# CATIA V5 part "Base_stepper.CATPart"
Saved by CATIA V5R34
Part number: Part1.1
Bounding box of the stored display mesh (mm): x -123.1 to 123.1, y -33.1 to 28.1, z -50 to 0
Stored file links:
  C:\Users\Apolinar\Desktop\cnc\Base_stepper.CATPart
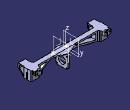
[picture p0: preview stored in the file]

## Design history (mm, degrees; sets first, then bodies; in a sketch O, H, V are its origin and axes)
AxisSystem1: origin (0, 0, 0), X (1, 0, 0), Y (0, 1, 0), Z (0, 0, 1)
Body1 (main body)
  DatumCurve1 to DatumCurve4
  Sketch1 on XY plane of AxisSystem1, origin (0, 0, 0), H (1, 0, 0), V (0, 1, 0)
    line L1 (-96.9, 10) -> (-96.9, 10.9787)
    line L2 (-99.0213, 13.1) -> (-120.9787, 13.1)
    line L3 (-123.1, 10.9787) -> (-123.1, 0)
    point P1 (-110, 0)
    arc A1 centre (-93.9, 10) radius 3 from (-93.9, 7) to (-96.9, 10) cw
    point P2 (-93.9, 7)
    point P3 (-96.9, 10)
    line L4 (-120.9787, 13.1) -> (-123.1, 10.9787)
    point P5 (-120.9787, 13.1)
    point P6 (-123.1, 10.9787)
    line L5 (-96.9, 10.9787) -> (-99.0213, 13.1)
    point P7 (-96.9, 10.9787)
    point P8 (-99.0213, 13.1)
    line L6 (-93.9, 7) -> (-93.9, 0)
    axis line L7 (-70.1752, 0) -> (-129.1057, 0)
    point P9 (-70.1752, 0)
    point P10 (-129.1057, 0)
    point P11 (-93.9, 0)
    point P12 (-123.1, 0)
    reference projected line E1 (-120, 3.75) -> (-120, 8.5) from edge of DatumCurve1
    point P13 (-93.9, -7)
    point P14 (-96.9, -10)
    point P16 (-120.9787, -13.1)
    point P17 (-123.1, -10.9787)
    point P18 (-96.9, -10.9787)
    point P19 (-99.0213, -13.1)
    line L8 (-96.9, -10) -> (-96.9, -10.9787)
    line L9 (-99.0213, -13.1) -> (-120.9787, -13.1)
    arc A2 centre (-93.9, -10) radius 3 from (-93.9, -7) to (-96.9, -10) ccw
    line L10 (-120.9787, -13.1) -> (-123.1, -10.9787)
    line L11 (-96.9, -10.9787) -> (-99.0213, -13.1)
    point P20 (-93.9, 0)
    line L12 (-93.9, -7) -> (-93.9, 0)
    point P21 (-123.1, 0)
    line L13 (-123.1, -10.9787) -> (-123.1, 0)
    point P22 (-110, 0)
    line L14 (-99.9, 10.1) -> (-99.9, -10.1)
    line L15 (-99.9, -10.1) -> (-120.1, -10.1)
    line L16 (-120.1, -10.1) -> (-120.1, 10.1)
    line L17 (-120.1, 10.1) -> (-99.9, 10.1)
    point P23 (-99.9, 10.1)
    point P24 (-99.9, -10.1)
    point P25 (-120.1, -10.1)
    point P26 (-120.1, 10.1)
    reference projected line E2 (-113.75, 10) -> (-118.5, 10) from edge of DatumCurve2
    reference projected line E3 (-100, -8.5) -> (-100, -3.75) from edge of DatumCurve3
    reference projected line E4 (-120, -8.5) -> (-120, -3.75) from edge of DatumCurve4
    point P27 (110, 0)
    point P28 (93.9, 7)
    point P29 (96.9, 10)
    point P31 (120.9787, 13.1)
    point P32 (123.1, 10.9787)
    point P33 (96.9, 10.9787)
    point P34 (99.0213, 13.1)
    point P35 (129.1057, 0)
    point P36 (93.9, 0)
    point P37 (123.1, 0)
    point P38 (93.9, -7)
    point P39 (96.9, -10)
    point P41 (120.9787, -13.1)
    point P42 (123.1, -10.9787)
    point P43 (96.9, -10.9787)
    point P44 (99.0213, -13.1)
    point P45 (93.9, 0)
    point P46 (123.1, 0)
    point P47 (110, 0)
    point P48 (99.9, 10.1)
    point P49 (99.9, -10.1)
    point P50 (120.1, -10.1)
    point P51 (120.1, 10.1)
    line L18 (96.9, 10) -> (96.9, 10.9787)
    line L19 (99.0213, 13.1) -> (120.9787, 13.1)
    line L20 (123.1, 10.9787) -> (123.1, 0)
    arc A3 centre (93.9, 10) radius 3 from (93.9, 7) to (96.9, 10) ccw
    line L21 (120.9787, 13.1) -> (123.1, 10.9787)
    line L22 (96.9, 10.9787) -> (99.0213, 13.1)
    line L23 (93.9, 7) -> (93.9, 0)
    line L24 (96.9, -10) -> (96.9, -10.9787)
    line L25 (99.0213, -13.1) -> (120.9787, -13.1)
    arc A4 centre (93.9, -10) radius 3 from (93.9, -7) to (96.9, -10) cw
    line L26 (120.9787, -13.1) -> (123.1, -10.9787)
    line L27 (96.9, -10.9787) -> (99.0213, -13.1)
    line L28 (93.9, -7) -> (93.9, 0)
    line L29 (123.1, -10.9787) -> (123.1, 0)
    line L30 (99.9, 10.1) -> (99.9, -10.1)
    line L31 (99.9, -10.1) -> (120.1, -10.1)
    line L32 (120.1, -10.1) -> (120.1, 10.1)
    line L33 (120.1, 10.1) -> (99.9, 10.1)
    radius A1 = 3
    angle L2 L4 = 45
    length L4 = 3
    angle L1 L5 = 45
    length L5 = 3
    distance L6 V = 93.9
    distance P2 H = 7
    distance E1 L3 = 3.1
    distance L17 E2 = 0.1
    distance L14 E3 = 0.1
    distance L16 E4 = 0.1
    distance L2 L17 = 3
    distance L14 P7 = 3
    vertical: L1 V, L3 V, L6 V, L14 V, L16 V
    horizontal: L2 H, L7 H, L15 H, L17 H
    coincidence: P1 H, P9 H, L7 P11, L7 P12, P22 L7, P11 P20, P12 P21, P36 P45, P37 P46
    tangency: A1 L1
    symmetry: P2 P13 H, P3 P14 H, P5 P16 H, P6 P17 H, P7 P18 H, P8 P19 H, L1 L8 H, L2 L9 H, A1 A2 H, L4 L10 H, L5 L11 H, P11 P20 H, L6 L12 H, P12 P21 H, L3 L13 H, P1 P27 V, P2 P28 V, P3 P29 V, P5 P31 V, P6 P32 V, P7 P33 V, P8 P34 V, P10 P35 V, P11 P36 V, P12 P37 V, P13 P38 V, P14 P39 V, P16 P41 V, P17 P42 V, P18 P43 V, P19 P44 V, P20 P45 V, P21 P46 V, P22 P47 V, P23 P48 V, P24 P49 V, P25 P50 V, P26 P51 V, L1 L18 V, L2 L19 V, L3 L20 V, A1 A3 V, L4 L21 V, L5 L22 V, L6 L23 V, L8 L24 V, L9 L25 V, A2 A4 V, L10 L26 V, L11 L27 V, L12 L28 V, L13 L29 V, L14 L30 V, L15 L31 V, L16 L32 V, L17 L33 V
    equidistance: L14 L16 P22, L15 L17 P22
  Pad1: profile Sketch1, direction (0, 0, -1), length 30
  Sketch2 on XY plane of AxisSystem1, origin (0, 0, 0), H (1, 0, 0), V (0, 1, 0)
    line L1 (93.9, 7) -> (93.9, -7)
    line L2 (93.9, -7) -> (-93.9, -7)
    line L3 (-93.9, -7) -> (-93.9, 7)
    line L4 (-93.9, 7) -> (93.9, 7)
    reference projected line E1 (-93.9, -7) -> (-93.9, 0) from edge [face of Pad1 from Sketch1.L12 | start face of Pad1]
    distance L2 L4 = 14
    vertical: L1 V, L3 V
    horizontal: L2 H, L4 H
    equidistance: L1 L3 O, L2 L4 O
    coincidence: L3 E1
  Pad2: profile Sketch2, direction (0, 0, -1), length 5
  Plane1: type Offset, RefPlane YZ plane of AxisSystem1, Offset 16
  Plane2: type Offset, RefPlane YZ plane of AxisSystem1, Offset 16, reversed
  Sketch3 on face of Pad1 from Sketch1.L3, origin (-123.1, 0, 0), H (0, -1, 0), V (0, 0, 1)
    construction line L1 (0, -12.5) -> (0, -30)
    point P1 (0, -12.5)
    point P2 (0, -30)
    line L2 (2.5, -12.5) -> (2.5, -30)
    line L3 (-2.5, -30) -> (-2.5, -12.5)
    arc A1 centre (0, -30) radius 2.5 from (2.5, -30) to (-2.5, -30) cw
    arc A2 centre (0, -12.5) radius 2.5 from (-2.5, -12.5) to (2.5, -12.5) cw
    reference projected line E1 (0, -30) -> (10.9787, -30) from edge [end face of Pad1 | face of Pad1 from Sketch1.L13]
    distance L1 L2 = 2.5
    distance A2 H = 10
    coincidence: P1 V, P2 E1
    vertical: L1 V
    tangency: A1 L2, A2 L2, A1 L3, A2 L3
  Pocket1: profile Sketch3, direction (1, 0, 0), length 10
  Mirror1: of Pocket1, about YZ plane of AxisSystem1
  Sketch4 on XY plane of AxisSystem1, origin (0, 0, 0), H (1, 0, 0), V (0, 1, 0)
    point P1 (-119.9, 13.1)
    line L1 (-119.9, 13.1) -> (-99.9, 13.1)
    line L2 (-99.9, 13.1) -> (-99.9, 28.1)
    line L3 (-99.9, 28.1) -> (-119.9, 28.1)
    line L4 (-119.9, 28.1) -> (-119.9, 22.1)
    point P2 (-99.9, 13.1)
    point P3 (-99.9, 28.1)
    point P4 (-119.9, 28.1)
    reference projected line E1 (-99.0213, 13.1) -> (-120.9787, 13.1) from edge [face of Pad1 from Sketch1.L2 | start face of Pad1]
    arc A1 centre (-106.9, 21.1) radius 4 from (-110.773, 20.1) to (-110.773, 22.1) ccw
    point P5 (-106.9, 21.1)
    reference projected line E2 (-99.9, -10.1) -> (-99.9, 10.1) from edge [start face of Pad1 | face of Pad1 from Sketch1.L14]
    point P6 (-113.9259, 18.1)
    line L5 (-110.773, 20.1) -> (-119.9, 20.1)
    line L6 (-119.9, 22.1) -> (-110.773, 22.1)
    point P7 (-110.773, 22.1)
    point P8 (-110.773, 20.1)
    point P9 (-119.9, 20.1)
    point P10 (-119.9, 22.1)
    line L7 (-119.9, 20.1) -> (-119.9, 13.1)
    point P11 (119.9, 13.1)
    point P12 (99.9, 13.1)
    point P13 (99.9, 28.1)
    point P14 (119.9, 28.1)
    point P16 (113.9259, 18.1)
    point P17 (110.773, 22.1)
    point P18 (110.773, 20.1)
    point P19 (119.9, 20.1)
    point P20 (119.9, 22.1)
    line L8 (119.9, 13.1) -> (99.9, 13.1)
    line L9 (99.9, 13.1) -> (99.9, 28.1)
    line L10 (99.9, 28.1) -> (119.9, 28.1)
    line L11 (119.9, 28.1) -> (119.9, 22.1)
    arc A2 centre (106.9, 21.1) radius 4 from (110.773, 20.1) to (110.773, 22.1) cw
    line L12 (110.773, 20.1) -> (119.9, 20.1)
    line L13 (119.9, 22.1) -> (110.773, 22.1)
    line L14 (119.9, 20.1) -> (119.9, 13.1)
    length L3 = 20
    length L2 = 15
    radius A1 = 4
    distance A1 L3 = 3
    distance A1 L2 = 3
    distance L5 P5 = 1
    distance P10 P5 V = 1
    horizontal: L1 H, L3 H, L5 H, L6 H
    vertical: L2 V, L4 V, L7 V
    coincidence: L1 E1, E2 L2, L4 L7
    symmetry: P1 P11 V, P2 P12 V, P3 P13 V, P4 P14 V, P6 P16 V, P7 P17 V, P8 P18 V, P9 P19 V, P10 P20 V, L1 L8 V, L2 L9 V, L3 L10 V, L4 L11 V, A1 A2 V, L5 L12 V, L6 L13 V, L7 L14 V
  Pad3: profile Sketch4, direction (0, 0, -1), length 10
  Chamfer1: length 4, angle 75, on edge [face of Pad3 from Sketch4.L3 | face of Pad3 from Sketch4.L4]
  Chamfer2: length 4, angle 45, on edge [face of Pad3 from Sketch4.L2 | face of Pad3 from Sketch4.L3]
  Chamfer3: length 0.8, angle 80, on edge [face of Pad1 from Sketch1.L2 | face of Pad3 from Sketch4.L2]
  Chamfer4: length 4, angle 75, on edge [face of Pad3 from Sketch4.L11 | face of Pad3 from Sketch4.L10]
  Chamfer5: length 4, angle 45, on edge [face of Pad3 from Sketch4.L10 | face of Pad3 from Sketch4.L9]
  Chamfer6: length 0.8, angle 80, on edge [face of Pad3 from Sketch4.L9 | face of Pad1 from Sketch1.L19]
  Sketch5 on face of Pad3 from Sketch4.L3, origin (0, 28.1, 0), H (-1, 0, 0), V (0, 0, 1)
    circle A1 centre (116.15, -5) radius 1.75
    point P1 (116.15, -5)
    reference projected line E1 (119.9, 0) -> (104.9718, 0) from edge [face of Pad3 | face of Chamfer1]
    reference projected line E2 (119.9, 0) -> (119.9, -10) from edge [face of Chamfer1 | face of Pad3 from Sketch4.L4]
    distance P1 E1 = 5
    distance A1 E2 = 2
    radius A1 = 1.75
  Pocket2: profile Sketch5, direction (0, -1, 0), length 15
  Sketch6 on face of Pad1 from Sketch1.L2, origin (0, 13.1, 0), H (-1, 0, 0), V (0, 0, 1)
    point P2 (116.15, -2.3)
    construction circle A1 centre (116.15, -5) radius 3.1177
    construction circle A2 centre (116.15, -5) radius 2.7
    point P3 (117.7088, -2.3)
    point P4 (114.5912, -2.3)
    point P5 (113.0323, -5)
    point P6 (114.5912, -7.7)
    point P7 (117.7088, -7.7)
    line L1 (117.7088, -2.3) -> (114.5912, -2.3)
    line L2 (114.5912, -2.3) -> (113.0323, -5)
    line L3 (113.0323, -5) -> (114.5912, -7.7)
    line L4 (114.5912, -7.7) -> (117.7088, -7.7)
    construction line L5 (116.15, -5) -> (116.15, -2.3)
    reference projected circle E1 centre (116.15, -5) radius 1.75 from edge [face of Chamfer1 | face of Pocket2 from Sketch5.A1]
    line L6 (117.7088, -2.3) -> (120.9787, -2.3)
    line L7 (120.9787, -2.3) -> (120.9787, -7.7)
    line L8 (120.9787, -7.7) -> (117.7088, -7.7)
    reference projected line E2 (120.9787, 0) -> (120.9787, -30) from edge [face of Pad1 from Sketch1.L2 | face of Pad1 from Sketch1.L4]
    distance L1 L4 = 5.4
    coincidence: A1 P3, A1 P4, A1 P5, A1 P6, A1 P7, E2 L7
    tangency: A2 L1, A2 L2, A2 L3, A2 L4, L6 A2
    midpoint: P2 L1
    vertical: L5 V, L7 V
    concentricity: A2 E1
    horizontal: L8 H
  Pocket3: profile Sketch6, direction (0, 1, 0), length 3
  Mirror2: of Pocket2, Pocket3, about YZ plane of AxisSystem1
  Fillet1: radius 2, on edge [face of Pad3 from Sketch4.L6 | face of Pad3 from Sketch4.A1]; edge [face of Pad3 from Sketch4.A1 | face of Pad3 from Sketch4.L5]
  Fillet2: radius 2, on edge [face of Pad3 from Sketch4.A2 | face of Pad3 from Sketch4.L13]; edge [face of Pad3 from Sketch4.L12 | face of Pad3 from Sketch4.A2]
  DatumCurve5 to DatumCurve8
  Sketch7 on end face of Pad2, origin (0, 0, -5), H (1, 0, 0), V (0, -1, 0)
    point P1 (10, 0)
    line L1 (12.5, 19) -> (12.5, -19)
    line L2 (12.5, -19) -> (7.5, -19)
    line L3 (7.5, -19) -> (7.5, 19)
    line L4 (7.5, 19) -> (12.5, 19)
    reference projected line E1 (93.9, 7) -> (93.9, 0) from edge [end face of Pad2 | face of Pad1 from Sketch1.L28]
    length L1 = 38
    length L4 = 5
    distance E1 L1 = 81.4
    coincidence: P1 H
    vertical: L1 V, L3 V
    horizontal: L2 H, L4 H
    equidistance: L1 L3 P1, L2 L4 P1
  Pad4: profile Sketch7, direction (0, 0, -1), length 45
  DatumPoint1
  Sketch8 on face of Pad4 from Sketch7.L3, origin (7.5, 0, 0), H (0, -1, 0), V (0, 0, 1)
    circle A1 centre (0, -30.5) radius 11.25
    point P1 (0, -30.5)
    reference projected line E1 (19, -50) -> (-19, -50) from edge [face of Pad4 from Sketch7.L3 | end face of Pad4]
    radius A1 = 11.25
    distance P1 E1 = 19.5
    coincidence: P1 V
  Pocket4: profile Sketch8, direction (1, 0, 0), through (limit type 6)
  Chamfer7: length 5, angle 67.3, on edge [start face of Pad4 | face of Pad2 from Sketch2.L4]; edge [start face of Pad4 | face of Pad2 from Sketch2.L2]
  Chamfer8: length 11.9, angle 70, on edge [face of Pad4 from Sketch7.L3 | face of Pad2 from Sketch2.L4]; edge [face of Pad4 from Sketch7.L3 | face of Pad2 from Sketch2.L2]; edge [face of Pad4 from Sketch7.L1 | face of Pad2 from Sketch2.L2]; edge [face of Pad4 from Sketch7.L1 | face of Pad2 from Sketch2.L4]
  DatumCurve9
  Sketch9 on face of Pad4 from Sketch7.L3, origin (7.5, 0, 0), H (0, -1, 0), V (0, 0, 1)
    circle A1 centre (-15.5, -14.5) radius 2
    point P1 (-15.5, -14.5)
    reference projected line E1 through (-19, 0) direction (0, -1) from edge of DatumCurve9
    construction line L1 (0, -8.1072) -> (0, -29.3359)
    point P2 (0, -8.1072)
    circle A2 centre (15.5, -14.5) radius 2
    point P5 (-15.5, -46)
    point P6 (0, -41.8928)
    circle A3 centre (-15.5, -46) radius 2
    reference projected line E2 (-19, -5) -> (-19, -50) from edge [face of Pad4 from Sketch7.L2 | face of Pad4 from Sketch7.L3]
    point P8 (0, -41.8928)
    circle A4 centre (15.5, -46) radius 2
    reference projected line E3 (19, -50) -> (-19, -50) from edge [face of Pad4 from Sketch7.L3 | end face of Pad4]
    radius A1 = 2
    distance A1 E1 = 1.5
    distance P1 P5 = 31.5
    distance A3 E2 = 1.5
    radius A3 = 2
    distance A3 E3 = 2
    coincidence: P2 V
    vertical: L1 V
    symmetry: A1 A2 L1, P6 P8 L1, A3 A4 L1
  Pocket5: profile Sketch9, direction (1, 0, 0), through (limit type 6)
  Fillet3: radius 5, on edge [face of Pad4 from Sketch7.L2 | end face of Pad4]; edge [face of Pad4 from Sketch7.L4 | end face of Pad4]
  Fillet4: radius 2, on edge [end face of Pad2 | face of Pad4 from Sketch7.L3]
  Chamfer9: length 25, angle 75, on edge [end face of Pad2 | face of Pad1 from Sketch1.L6]
  Sketch10 on face of Pad2 from Sketch2.L4, origin (0, 7, 0), H (-1, 0, 0), V (0, 0, 1)
    line L1 (88.9, -23.4839) -> (88.9, -5)
    line L2 (88.9, -5) -> (19.9172, -5)
    line L3 (19.9172, -5) -> (88.9, -23.4839)
    reference projected line E1 (-93.9, 0) -> (93.9, 0) from edge [face of Pad2 from Sketch2.L4 | face of Pad3]
    reference projected line E2 (93.9, 0) -> (93.9, -5) from edge [face of Pad2 from Sketch2.L4 | face of Pad1 from Sketch1.A1]
    reference projected line E3 (45.6037, -17.059) -> (93.9, -30) from edge [face of Chamfer9 | face of Pad2 from Sketch2.L4]
    distance L2 E1 = 5
    distance L1 E2 = 5
    distance L3 E3 = 5
  Pocket6: profile Sketch10, direction (0, -1, 0), through (limit type 6)
  Chamfer10: length 25, angle 55, on edge [end face of Pad2 | face of Pad1 from Sketch1.L23]
  Sketch11 on face of Pad1 from Sketch1.L9, origin (0, -13.1, 0), H (1, 0, 0), V (0, 0, 1)
  Pad5: profile Sketch11, direction (0, -1, 0), length 20
  Chamfer11: length 20, angle 45, on edge [face of Pad5 | end face of Pad5] (x2)
  Chamfer12: length 3, angle 45, on edge [face of Pad5 | end face of Pad5] (x6)
  Sketch12 on face of Pad5, origin (-120.9787, 0, 0), H (0, -1, 0), V (0, 0, 1)
    line L1 (13.1, -25.7574) -> (13.1, -3)
    line L2 (13.1, -3) -> (27.1, -3)
    line L3 (27.1, -3) -> (27.1, -11.7574)
    line L4 (27.1, -11.7574) -> (13.1, -25.7574)
    reference projected line E1 (13.1, 0) -> (33.1, 0) from edge [face of Pad5 | face of Pad5]
    reference projected line E2 (30.1, 0) -> (30.1, -13) from edge [face of Pad5 | face of Chamfer12]
    reference projected line E3 (33.1, -10) -> (13.1, -30) from edge [face of Pad5 | face of Chamfer11]
    reference projected line E4 (13.1, 0) -> (13.1, -30) from edge [face of Pad1 from Sketch1.L10 | face of Pad5]
    distance L2 E1 = 3
    distance L3 E2 = 3
    distance L4 E3 = 3
    vertical: L1 V, L3 V
    horizontal: L2 H
    coincidence: L1 E4
  Pocket7: profile Sketch12, direction (1, 0, 0), through (limit type 6)
  Mirror3: of Pocket7, about YZ plane of AxisSystem1
  Sketch13 on face of Pad5, origin (0, 0, 0), H (1, 0, 0), V (0, 1, 0)
    projected line E1 (-120.1, 10.1) -> (-120.1, -10.1) from edge [face of Pad5 | face of Pad1 from Sketch1.L16]
    projected line E2 (-99.9, 10.1) -> (-120.1, 10.1) from edge [face of Pad5 | face of Pad1 from Sketch1.L17]
    projected line E3 (-99.9, -10.1) -> (-99.9, 10.1) from edge [face of Pad5 | face of Pad1 from Sketch1.L14]
    projected line E4 (-120.1, -10.1) -> (-99.9, -10.1) from edge [face of Pad5 | face of Pad1 from Sketch1.L15]
    projected line E5 (99.9, -10.1) -> (120.1, -10.1) from edge [face of Pad5 | face of Pad1 from Sketch1.L31]
    projected line E6 (99.9, 10.1) -> (99.9, -10.1) from edge [face of Pad5 | face of Pad1 from Sketch1.L30]
    projected line E7 (120.1, 10.1) -> (99.9, 10.1) from edge [face of Pad5 | face of Pad1 from Sketch1.L33]
    projected line E8 (120.1, -10.1) -> (120.1, 10.1) from edge [face of Pad5 | face of Pad1 from Sketch1.L32]
  Pad6: profile Sketch13, direction (0, 0, -1), length 3
  Sketch14 on face of Pad2 from Sketch2.L4, origin (0, 7, 0), H (-1, 0, 0), V (0, 0, 1)
    line L1 (-88.9, -20.3951) -> (-88.9, -5)
    line L2 (-88.9, -5) -> (-66.9135, -5)
    line L3 (-66.9135, -5) -> (-88.9, -20.3951)
    reference projected line E1 through (-93.9, 0) direction (0, 1) from axis of face of Pad1 from Sketch1.A3
    reference projected line E2 (-93.9, -30) -> (-58.1963, -5) from edge [face of Chamfer10 | face of Pad2 from Sketch2.L4]
    reference projected line E3 (-93.9, 0) -> (93.9, 0) from edge [face of Pad2 from Sketch2.L4 | face of Pad6]
    distance L1 E1 = 5
    distance L3 E2 = 5
    distance L2 E3 = 5
    vertical: L1 V
    horizontal: L2 H
  Pocket8: profile Sketch14, direction (0, -1, 0), through (limit type 6)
